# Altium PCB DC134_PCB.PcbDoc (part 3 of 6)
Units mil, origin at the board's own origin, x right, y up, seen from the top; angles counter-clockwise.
Board outline 4000 x 2750 mil, 6 copper layers (L1_Top Layer, L2_GND1, L3_Signal, L4_Plane, L5_GND2, L6_Bottom Layer), stack 60.4 mil thick; 404 components, 244 nets, 1547 pads, 694 vias.
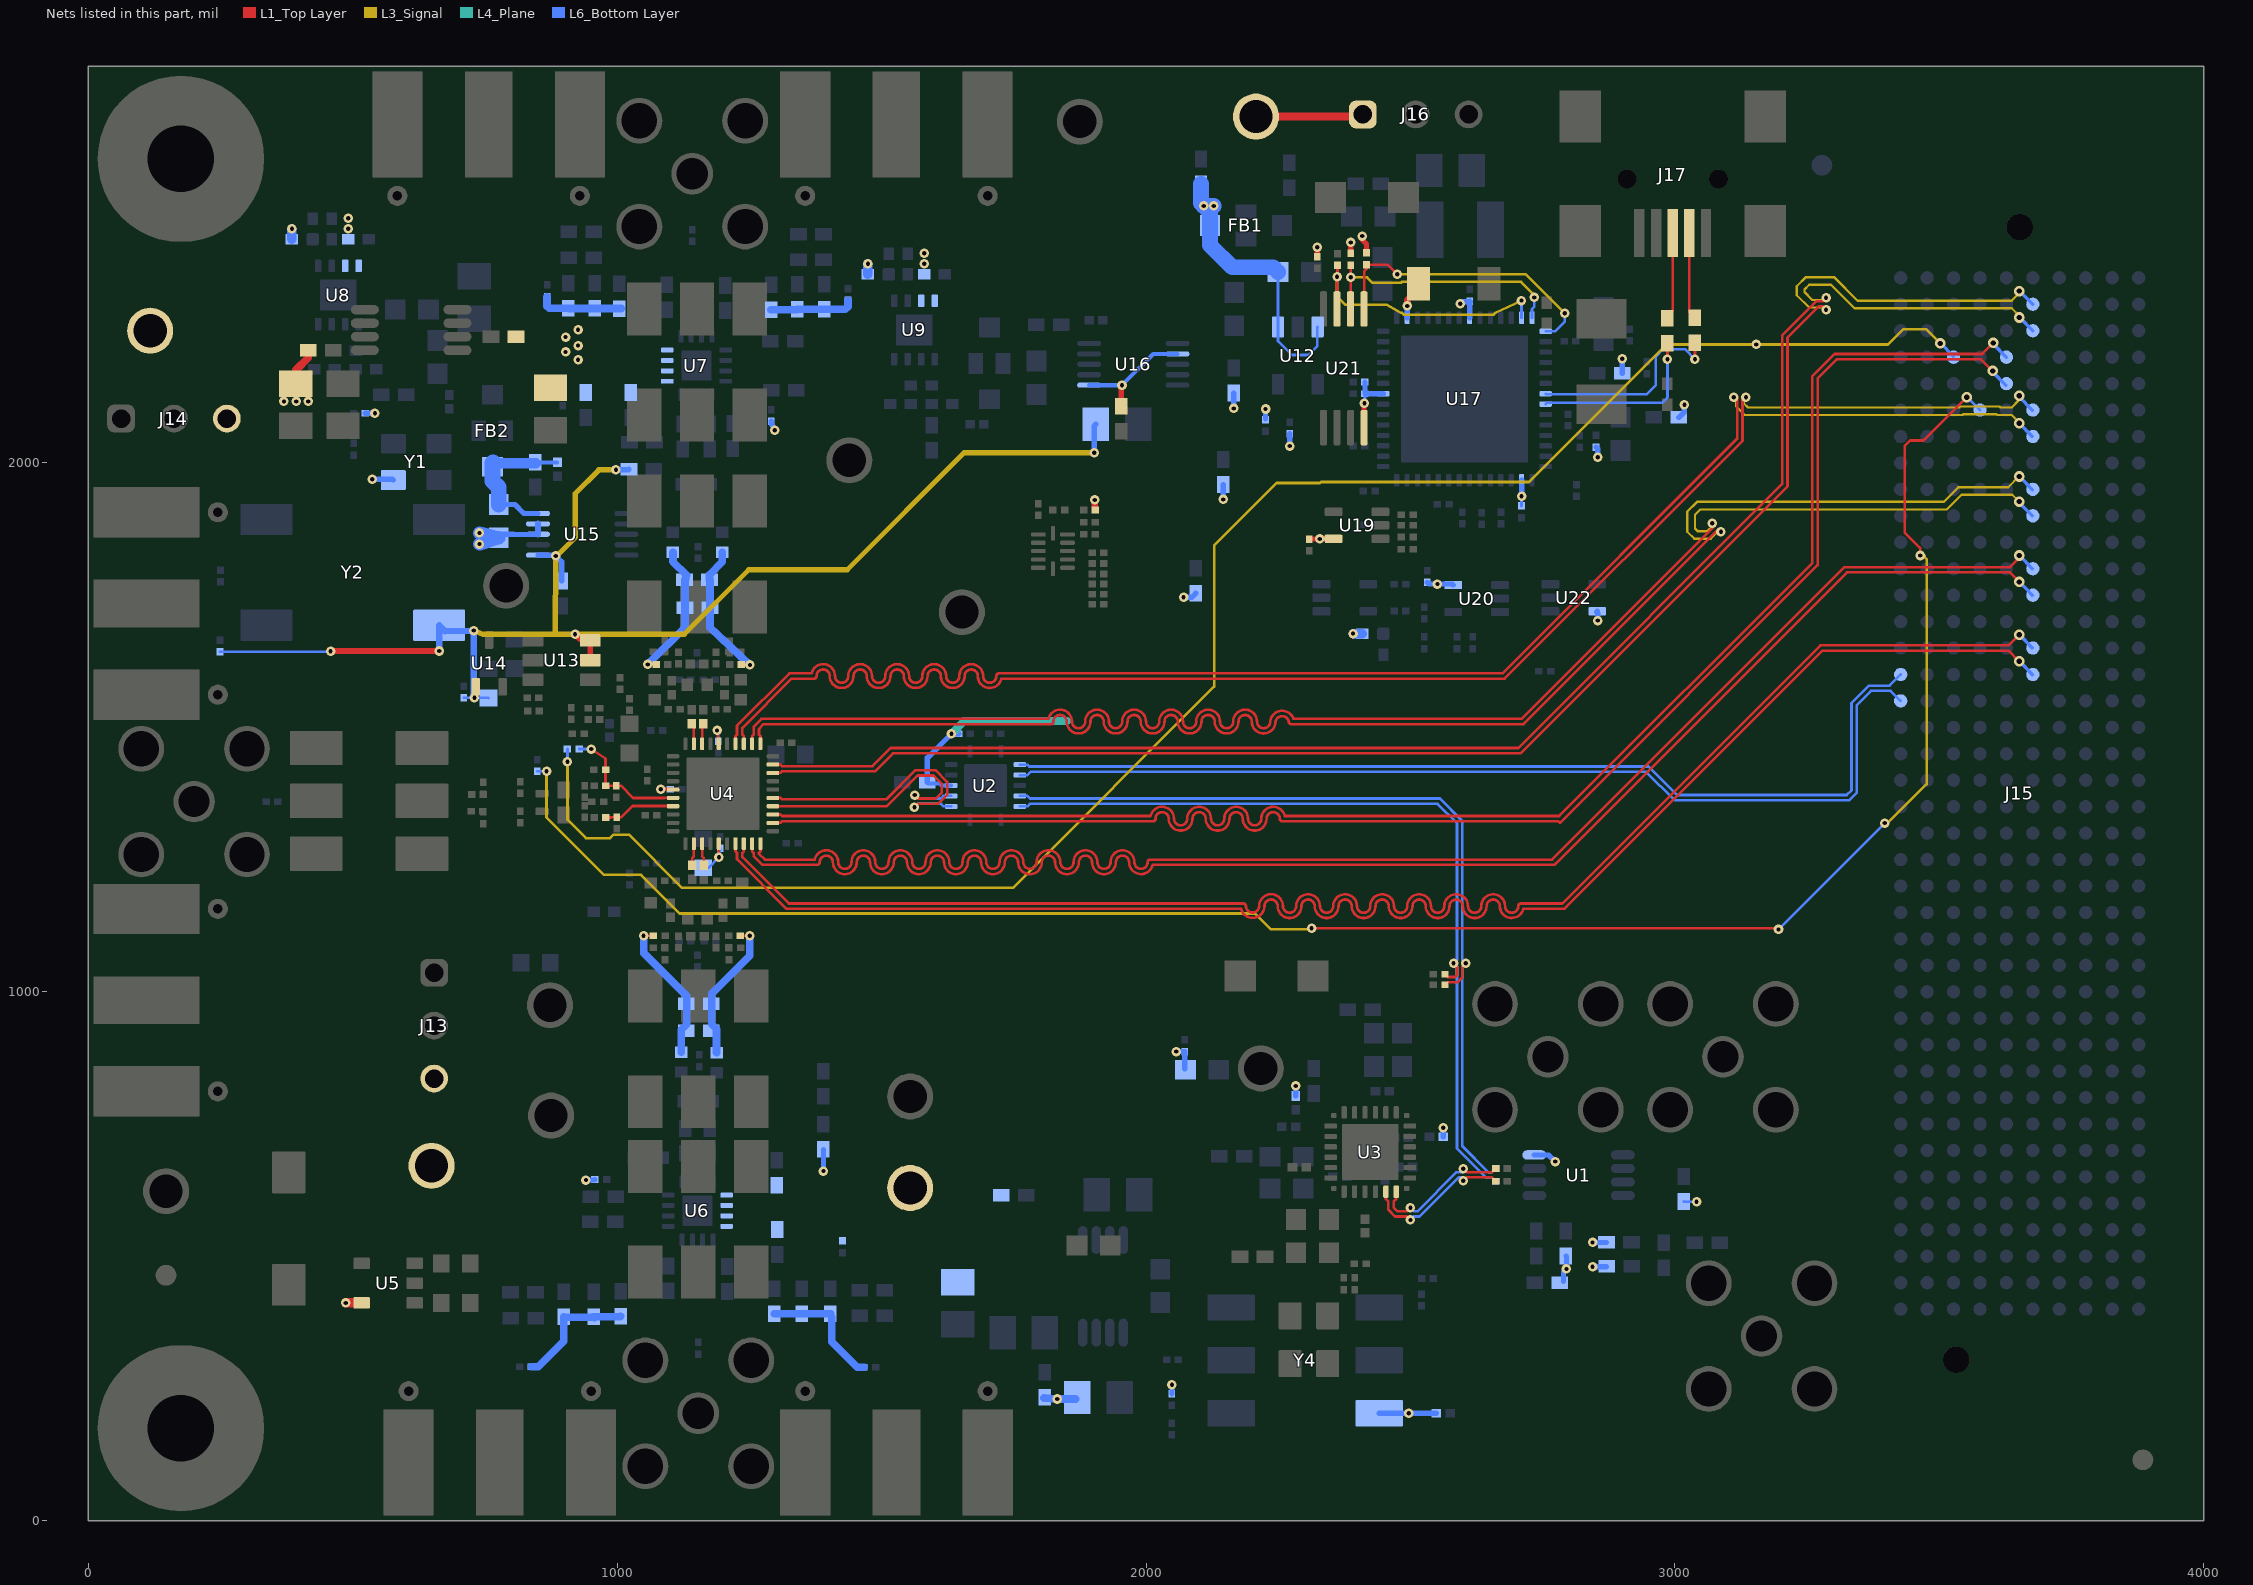
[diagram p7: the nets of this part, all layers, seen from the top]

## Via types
v1: diameter 18, hole 8, L1_Top Layer to L6_Bottom Layer, tented both sides, 448 vias
v2: diameter 20, hole 10, L1_Top Layer to L6_Bottom Layer, tented both sides, 182 vias
v3: diameter 19.68, hole 7.87, L1_Top Layer to L6_Bottom Layer, tented both sides, 42 vias
v4: diameter 19.68, hole 7.87, L1_Top Layer to L6_Bottom Layer, 20 vias
v5: diameter 18, hole 8, L1_Top Layer to L6_Bottom Layer, 2 vias

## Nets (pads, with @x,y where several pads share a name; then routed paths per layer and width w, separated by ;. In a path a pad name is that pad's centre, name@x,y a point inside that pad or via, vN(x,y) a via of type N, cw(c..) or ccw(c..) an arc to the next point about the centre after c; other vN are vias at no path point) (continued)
+3.3V: C18.2 C19.2 C20.2 C22.2 C30.1 C85.1 C86.2 C93.1 C95.1 C97.1 C99.1 C100.1 C102.1 C103.1 C104.1 C105.2 C106.2 C107.2 C120.2 C121.1 C122.1 C123.1 L18.2 L19.1 L20.1 R34.2 R38.2 R42.2 R52.2 R56.2 R57.1 R66.2 R72.2 R85.2 R93.2 R102.2 R108.2 R125.1 R126.1 R152.1 R155.1 R156.2 R157.2 R160.2 R161.2 R162.2 R173.1 U1.8 U2.4 U13.5 U13.6 U14.1 U15.6 U16.2 U16.6 U17.16 U17.36 U17.44 U17.50 U19.5 U20.5 U21.8 U22.5 Y2.4 Y4.6 | length 4585.1
  L1_Top Layer w5: v1@2412.39,2112.39 v1(2413,2113)
  L1_Top Layer w10: v1(920.5,1676) 930.1,1666.4 949.13,1666.4 U13.6@949.13,1664.4 U13.5@949.13,1629 ; C103.1@1954,2108.12 C103.1@1953,2107.12 1953,2145.5 v1(1954.63,2147.13) ; C121.1@2310.39,1856.02 v1@2328,1856.02 ; R162.2@2324,2390.02 v1(2324,2408) ; v1(2328.39,1856.41) U19.5@2354.71,1856.41 U19.5@2356.5,1856.41 ; R161.2@2387,2398.02 v1(2387,2417) ; v1(2409,2429) 2409,2422 2417,2414 R160.2@2417,2397.02 ; U21.8@2412.39,2066.8 v1@2412.39,2112.39
  L1_Top Layer w12: v1(458,1644) 458.39,1644.39 v1(663.39,1644.39) ; R152.1@1903,1910.98 v1(1903,1930) ; v1(2494,2297) 2494,2308 2515.07,2329.07 C104.1@2515.07,2339
  L1_Top Layer w15: C95.1@392.5,2150.01 392.5,2175.73 415.88,2199.11 R126.1@415.88,2213.01
  L3_Signal w10: v1(729,1683) 747,1676 883,1676 ; v1(997.62,1987) 965.38,1987 920.75,1942.38 920.75,1858.96 885.87,1824.08 v1(884,1824.08) 883,1676 ; v1(1902,2019.41) 1656.41,2019.41 1435,1798 1248.74,1798 1126.74,1676 v1(920.5,1676) 883,1676
  L4_Plane w15: v1(1632.19,1488) 1656.19,1512 1851,1512
  L6_Bottom Layer w5: R38.2@249,1642.95 v1@458,1642.95 ; C97.1@709.78,1555.98 v1(730,1555.98) 756.25,1555.98 C99.1@756.78,1555.44 ; v1@882.37,1825.71 v1(884,1824.08) ; v1(2413,2113) 2414.02,2114.02 C107.2@2414.02,2131 ; C106.2@2710,1918.61 2710,1936.71 v1(2710.29,1937) ; C22.2@3017,603.53 v1(3041,603)
  L6_Bottom Layer w8: C18.2@1586.62,1396 1588.62,1394 1610,1394 1613.96,1390.04 U2.4@1631.51,1390.04 ; U16.6@1892.34,2147.13 v1(1954.63,2147.13) 2013.69,2206.18 U16.2@2059.66,2206.18
  L6_Bottom Layer w10: U15.6@850.34,1825.71 v1@882.37,1825.71 ; v1(884,1824.08) 895,1813.08 C102.1@895,1776.62 ; v1(941,644) 956.98,644 R93.2@957.98,645 ; v1(997.62,1987) 1021.28,1987 R102.2@1022.28,1988 ; R108.2@1291.38,2078.98 1291.38,2073.6 1298,2063.35 v1(1298,2062) ; v1(1390,661) R85.2@1390,701.38 ; C18.2@1586.62,1396 1586.62,1442.43 v1(1632.19,1488) R52.2@1645.98,1488 ; v1(1902,2019.41) 1902,2070 C85.1@1905,2073 ; R66.2@2049,240.02 v1(2049,257) ; v1(2057,886.98) C100.1@2073,886.98 R57.1@2073,854.13 ; v1(2071,1746) 2086.62,1746 R156.2@2094,1753.38 ; v1(2146,1931) R157.2@2146,1959.38 ; v1(2166,2103) L18.2@2166,2132.38 ; C123.1@2226,2083.11 v1(2226,2102) ; v1(2272,2032) 2272,2054.89 C86.2@2272.09,2054.98 ; R56.2@2283,802.99 v1(2283,822) ; C120.2@2414.02,2153.12 C107.2@2414.02,2131 2448.32,2131 U17.36@2448.47,2130.84 ; Y4.6@2440.96,203 v1(2497,203) C30.1@2549.01,203 ; U17.44@2493.75,2274.54 2494,2274.79 v1(2494,2297) ; C122.1@2532,1773.98 2534.98,1771 v1(2551,1771) 2579.03,1771 U20.5@2580.82,1769.21 ; R72.2@2561.99,726 v1(2561.99,743.01) ; v1@2596,2305 C105.2@2612,2305 ; U17.50@2611.86,2274.54 2612,2274.68 C105.2@2612,2305 ; v1(2710.29,1937) U17.16@2710.29,1967.46 ; U1.8@2734.34,691.54 2761.44,691.54 v1(2774,678.98) ; C19.2@2789.62,452 2789.62,470.62 v1(2795,476) 2795,499.38 R42.2@2794,500.38 ; v1(2844.38,480.02) C20.2@2870.76,480.02 ; v1(2844.38,526) R34.2@2870.76,526 ; R155.1@2851,2029.98 2854,2026.98 v1(2854,2010.62) ; U22.5@2853.29,1719.41 2852,1718.12 2854,1716.12 v1(2854,1702) ; L20.1@2900.62,2169.5 v1(2900.62,2197) ; L19.1@3007.62,2086 3018,2096.38 v1(3018,2110) ; C105.2@2612,2305 2612.98,2305 C105.2@2612,2305.98 C105.2@2612,2305
  L6_Bottom Layer w12: v1(663.39,1644.39) Y2.4@663.39,1693 674.41,1681.98 v1(729,1683) ; v1(729,1683) 729.05,1556.93 v1(730,1555.98)
  L6_Bottom Layer w15: R125.1@1807.22,231.62 v1(1832,230) C93.1@1867,230
  L6_Bottom Layer w18: v1(2391.66,1677.34) R173.1@2409.29,1677.34
  other v1: 370,2116.22 393,2116.22 415.88,2116.22 2594,2301
+5V: C70.1 C73.2 C77.2 C83.1 FB1.3 R116.2 R118.2 U8.7 U8.8 U9.7 U9.8 U12.1 U12.3 | length 590.4
  L6_Bottom Layer w5: C83.1@2249.5,2361 2249.5,2257.23 U12.1@2249.6,2257.13 2249.6,2230.4 2276,2204 2307,2204 2324,2221 2324,2256.73 U12.3@2324.4,2257.13
  L6_Bottom Layer w18: R116.2@385.11,2422.62 v1(385.11,2442.62) ; R118.2@1474.24,2356.65 v1(1474.24,2376.65)
  L6_Bottom Layer w30: C70.1@2104,2527.38 2104,2491 v1(2109,2486) ; v1(2128,2486) v1(2109,2486) ; C83.1@2249.5,2361 2240.5,2370 2163,2370 2121.09,2411.91 FB1.3@2121.09,2449 2121.09,2473.91 v1(2109,2486)
  other v1: 1580.5,2376.65 1580.5,2396.65 491.37,2442.62 491.37,2462.62
+5V_EXT: J16.1 TP13.1 | length 203.7
  L1_Top Layer w15: TP13.1@2208,2655 2406,2655 J16.1@2410,2659
-0.23V_CHA: C59.1 C60.1 C88.1 R95.2 R123.2 TP10.1 U6.13 U6.14 U6.15 U6.16
-0.23V_CHB: C61.1 C62.1 C90.1 R112.2 R124.2 TP12.1 U7.13 U7.14 U7.15 U7.16
  other v1: 926,2195 902.56,2210 926,2222 902.44,2238 926,2252
AIN_N: R5.2 U4.13 | length 38.8
  L1_Top Layer w5: U4.13@1160.75,1279.54 1160.75,1255.63 1163.85,1252.53 R5.2@1163.85,1242.02
AIN_P: R12.2 U4.12 | length 38.8
  L1_Top Layer w5: R12.2@1141.35,1242.02 1141.9,1252.53 1145,1255.63 U4.12@1145,1279.54
AMP_CHA_IN_N: R13.1 R88.1 R91.2 R92.2 | length 235
  L6_Bottom Layer w14.5: R13.1@838.02,291 850.98,291 899,339.02 R91.2@899,385.38 ; R91.2@901.45,384.38 957.45,384.38 R92.2@957.16,384.02 ; R92.2@955.5,385.38 1005.38,385.38 R88.1@1006.38,386.38
AMP_CHA_IN_P: R2.1 R82.1 R83.1 R86.1 | length 232.8
  L6_Bottom Layer w14.5: R86.1@1297.62,391.24 R83.1@1349.38,391.24 ; R83.1@1349.51,391.38 R82.1@1403.38,391.38 ; R82.1@1405.72,384.38 1405.72,338.02 1453.75,290 R2.1@1466.7,290
AMP_CHA_OUT_N: C52.2 L12.2 R14.1 R87.1 | length 277.1
  L1_Top Layer w5: v1(1050,1106) R14.1@1068.55,1106
  L6_Bottom Layer w14.5: v1(1050,1106) 1050,1073.38 1131.38,992 1131.38,938.38 1120.95,927.95 1120.95,886.26 L12.2@1121.51,885.7
AMP_CHA_OUT_P: C52.1 L11.2 R1.1 R87.2 | length 273.3
  L1_Top Layer w5: R1.1@1232.76,1106 v1(1250.74,1106)
  L6_Bottom Layer w14.5: L11.2@1188.56,884.7 1188,885.26 1188,929 1178.62,938.38 1178.62,996 1250.74,1068.12 v1(1250.74,1106)
AMP_CHB_IN_N: R27.1 R105.1 R109.2 R110.2 | length 160
  L6_Bottom Layer w14.5: R105.1@1291,2289.38 1340,2289.38 R109.2@1341,2290.38 R110.2@1392,2290.38 1431.38,2290.38 1436.5,2295.5 R27.1@1436.5,2307.48
AMP_CHB_IN_P: R16.1 R99.1 R100.1 R103.1 | length 159.2
  L6_Bottom Layer w14.5: R16.1@867.5,2314.48 867.5,2296.5 871.62,2292.38 R99.1@907.7,2292.38 ; R99.1@908.7,2292 R103.1@1008,2292
AMP_CHB_OUT_N: C57.2 L14.2 R28.1 R104.1 | length 256.5
  L6_Bottom Layer w14.5: C57.2@1174.69,1779 1174.69,1788.69 1199.04,1813.04 L14.2@1199.04,1831.3 ; R104.1@1175.69,1727.07 C57.2@1175.69,1779 ; R104.1@1176.69,1727.07 R104.1@1175.62,1726 1175.5,1689 v1(1251,1618)
AMP_CHB_OUT_P: C57.1 L13.2 R15.1 R104.2 | length 251.1
  L6_Bottom Layer w14.5: v1(1058,1619) 1128.38,1689.38 R104.2@1128.38,1726 ; L13.2@1105.47,1831.3 1105.47,1813.53 C57.1@1131.45,1787.55 ; R104.2@1128.45,1727.07 C57.1@1128.45,1779 ; C57.1@1129.45,1779 C57.1@1129.45,1787.55
AVDD: C40.1 C41.1 C42.1 C43.1 J13.3 J14.3 R31.2 R133.1 TP6.1 U4.5 U4.15 U4.36 U5.5 U15.8 U15.9 Y1.4 | length 451.9
  L1_Top Layer w5: v1(1189,1494.09) U4.36@1192.13,1469.49 ; U4.15@1192.24,1280.06 1192.24,1263 1193,1262.24 v1@1193,1255
  L1_Top Layer w7: v1(1082.5,1383) U4.5@1105.63,1382.42
  L1_Top Layer w10: v1(1189,1494.09) v1@1190.32,1492.78
  L1_Top Layer w18: v1(486.8,411.6) U5.5@516.8,411.6
  L6_Bottom Layer w5: C43.1@1163,1234.44 1172.44,1234.44 v1(1192.56,1254.56) C41.1@1195,1270.98 ; C42.1@1191,1474.02 v1@1191,1492.09 ; C41.1@1192.56,1270.54 C41.1@1193,1270.98
  L6_Bottom Layer w7.5: v1(1082.5,1383) C40.1@1099.98,1383
  L6_Bottom Layer w10: R31.2@523.07,2094.07 R31.2@524.07,2094.07 v1(542,2094) ; v1(537,1969) 575.24,1969 Y1.4@576.69,1967.55 ; v1(739.5,1846.58) v1(739.5,1867.58) ; R133.1@776,1858.58 782.5,1865.08 804.1,1865.08 804.42,1864.76 850.02,1864.76 U15.8@850.34,1865.08 ; v1(1189,1494.09) v1@1191,1492.09
  L6_Bottom Layer w12: U15.8@850.34,1865.08 U15.9@850.34,1884.76
  L6_Bottom Layer w25: v1(739.5,1846.58) 745.73,1848.63 R133.1@776,1858.58 744.38,1866.38 v1(739.5,1867.58)
AVDD+: C75.1 C76.1 FB2.3 R133.2 U15.10 | length 285
  L6_Bottom Layer w7: C75.1@845,2001.62 845.63,2000.99 C76.1@887,2000.99
  L6_Bottom Layer w10: R133.2@776,1921.57 806.5,1921.57 823.39,1904.69 U15.10@850.34,1904.45
  L6_Bottom Layer w20: FB2.3@769.09,1999.47 C75.1@846.38,1999.47
  L6_Bottom Layer w30: FB2.3@765,2000.59 764.29,1999.88 764.29,1965.71 776,1954 R133.2@776,1921.57
BIN_N: R26.2 U4.38 | length 38.2
  L1_Top Layer w5: U4.38@1160.75,1474.09 1160.75,1498 1163.85,1501.1 R26.2@1165,1510.98
BIN_P: R19.2 U4.39 | length 38.4
  L1_Top Layer w5: R19.2@1139.98,1510.98 1141.9,1501.1 1145,1498 U4.39@1145,1474.09
CLK_N: C26.2 R54.2 U4.7 | length 136.1
  L1_Top Layer w5: C26.2@978.46,1329.63 988.05,1329.63 988.65,1330.22 R54.2@999,1330.22 1007.8,1330.22 1028.95,1351.38 U4.7@1105.51,1351.38
CLK_P: C21.2 R30.2 R41.2 R46.2 U4.6 | length 246.7
  L1_Top Layer w5: v1(951,1459) 978.02,1441 R30.2@978.02,1420 C21.2@978.02,1390.11 ; C21.2@978.46,1389.67 R46.2@998.44,1389.67 1007.24,1389.67 1030.41,1366.5 1089.33,1366.5 1089.96,1367.13 U4.6@1105.51,1367.13
  L1_Top Layer w12: v1(951,1459) v1@953.87,1459 ; C21.2@978.02,1390.11 C21.2@978.46,1389.67
  L6_Bottom Layer w5: R41.2@928.02,1459 v1(951,1459)
DA0_N: J15.E13 U4.19 | length 3053.9
  L1_Top Layer w5: U4.19@1255.24,1280.06 1255.24,1265.74 1258.11,1262.87 1258.11,1256.86 1274.97,1240 1378,1240 ccw(c1378,1245) 1383,1245 cw(c1395.5,1245) 1408,1245 ccw(c1430.5,1245) 1453,1245 cw(c1465.5,1245) 1478,1245 ccw(c1500.5,1245) 1523,1245 cw(c1535.5,1245) 1548,1245 ccw(c1570.5,1245) 1593,1245 cw(c1605.5,1245) 1618,1245 ccw(c1640.5,1245) 1663,1245 cw(c1675.5,1245) 1688,1245 ccw(c1710.5,1245) 1733,1245 cw(c1745.5,1245) 1758,1245 ccw(c1780.5,1245) 1803,1245 cw(c1815.5,1245) 1828,1245 ccw(c1850.5,1245) 1873,1245 cw(c1885.5,1245) 1898,1245 ccw(c1920.5,1245) 1943,1245 cw(c1955.5,1245) 1968,1245 ccw(c1990.5,1245) 2012.44,1240 2772.14,1240 2775.07,1242.93 3325.14,1793 3634,1793 3651,1776 v2(3651,1775)
  L6_Bottom Layer w6.6: v2@3652,1775 J15.E13@3676,1750.15
DA0_P: J15.E12 U4.20 | length 3041.3
  L1_Top Layer w5: U4.20@1270.98,1280.06 1270.98,1265.74 1268.11,1262.87 1268.11,1261 1279.11,1250 1373.56,1250 cw(c1395.5,1245) 1418,1245 ccw(c1430.5,1245) 1443,1245 cw(c1465.5,1245) 1488,1245 ccw(c1500.5,1245) 1513,1245 cw(c1535.5,1245) 1558,1245 ccw(c1570.5,1245) 1583,1245 cw(c1605.5,1245) 1628,1245 ccw(c1640.5,1245) 1653,1245 cw(c1675.5,1245) 1698,1245 ccw(c1710.5,1245) 1723,1245 cw(c1745.5,1245) 1768,1245 ccw(c1780.5,1245) 1793,1245 cw(c1815.5,1245) 1838,1245 ccw(c1850.5,1245) 1863,1245 cw(c1885.5,1245) 1908,1245 ccw(c1920.5,1245) 1933,1245 cw(c1955.5,1245) 1978,1245 ccw(c1990.5,1245) 2003,1245 cw(c2008,1245) 2008,1250 2768,1250 3321,1803 3634,1803 3651,1820 v2(3651,1825)
  L6_Bottom Layer w6.6: v2@3652,1825 J15.E12@3676,1800.15
DA1_N: J15.E16 U4.17 | length 3034.6
  L1_Top Layer w5: U4.17@1223.74,1280.06 1223.74,1265.74 1226.61,1262.87 1226.61,1250.86 1320.47,1157 2179.64,1157 ccw(c2201.5,1162.32) 2224,1161.91 ; 2224,1162 cw(c2236.5,1162) 2249,1162 ccw(c2271.5,1162) 2294,1162 cw(c2306.5,1162) 2319,1162 ccw(c2341.5,1162) 2364,1162 cw(c2376.5,1162) 2389,1162 ccw(c2411.5,1162) 2434,1162 cw(c2446.5,1162) 2459,1162 ccw(c2481.5,1162) 2504,1162 cw(c2516.5,1162) 2529,1162 ccw(c2551.5,1162) 2574,1162 cw(c2586.5,1162) 2599,1162 ccw(c2621.5,1162) 2644,1162 cw(c2656.5,1162) 2669,1162 ccw(c2691.5,1162) 2713.44,1157 2791.49,1157 2794.42,1159.93 3279.49,1645 3631,1645 3651,1625 v2(3651,1624.78)
  L6_Bottom Layer w6.6: v2@3652,1624.78 J15.E16@3676,1599.92
DA1_P: J15.E15 U4.18 | length 3021.3
  L1_Top Layer w5: U4.18@1239.49,1280.06 1239.49,1265.74 1236.61,1262.87 1236.61,1255 1324.61,1167 2184,1167 cw(c2184,1162) 2189,1162.09 ; 2189,1162 ccw(c2184,1162) 2189,1162.09 ; 2214,1162 cw(c2236.5,1162) 2214,1162.05 ; v2(3651,1675) 3631,1655 3275.35,1655 2787.35,1167 2709,1167 ccw(c2709,1162) 2704,1162 cw(c2691.5,1162) 2679,1162 ccw(c2656.5,1162) 2634,1162 cw(c2621.5,1162) 2609,1162 ccw(c2586.5,1162) 2564,1162 cw(c2551.5,1162) 2539,1162 ccw(c2516.5,1162) 2494,1162 cw(c2481.5,1162) 2469,1162 ccw(c2446.5,1162) 2424,1162 cw(c2411.5,1162) 2399,1162 ccw(c2376.5,1162) 2354,1162 cw(c2341.5,1162) 2329,1162 ccw(c2306.5,1162) 2284,1162 cw(c2271.5,1162) 2259,1162 ccw(c2236.5,1162) 2214,1162.05 ; 2189,1162.09 ccw(c2201.5,1162.32) 2214,1162.05
  L6_Bottom Layer w6.6: v2@3652,1675 J15.E15@3676,1650.15
DB0_N: J15.E10 U4.32 | length 3005.6
  L1_Top Layer w5: U4.32@1255.24,1469.03 1255.24,1483.34 1258.11,1486.22 1258.11,1501.14 1272.97,1516 1815.56,1516 cw(c1837.5,1511) 1860,1511 ccw(c1872.5,1511) 1885,1511 cw(c1907.5,1511) 1930,1511 ccw(c1942.5,1511) 1955,1511 cw(c1977.5,1511) 2000,1511 ccw(c2012.5,1511) 2025,1511 cw(c2047.5,1511) 2070,1511 ccw(c2082.5,1511) 2095,1511 cw(c2117.5,1511) 2140,1511 ccw(c2152.5,1511) 2165,1511 cw(c2187.5,1511) 2210,1511 ccw(c2222.5,1511) 2235,1511 ; 2235.04,1511.65 cw(c2257.5,1508.72) 2278.95,1516 2710,1516 3074,1880 3074,1883 v1(3070.9,1886.1)
  L3_Signal w4.4: v1(3070.9,1886.1) 3070.9,1880.02 3061.94,1871.06 3042.94,1871.06 3038,1876 3038,1902 3048,1912 3514.29,1912 3542.1,1939.82 3638,1939.82 v2(3651,1927)
  L6_Bottom Layer w6.6: v2@3651,1925 J15.E10@3676,1900
DB0_P: J15.E9 U4.31 | length 3062.8
  L1_Top Layer w5: U4.31@1270.98,1469.03 1270.98,1483.34 1268.11,1486.22 1268.11,1497 1277.11,1506 1820,1506 ccw(c1820,1511) 1825,1511 cw(c1837.5,1511) 1850,1511 ccw(c1872.5,1511) 1895,1511 cw(c1907.5,1511) 1920,1511 ccw(c1942.5,1511) 1965,1511 cw(c1977.5,1511) 1990,1511 ccw(c2012.5,1511) 2035,1511 cw(c2047.5,1511) 2060,1511 ccw(c2082.5,1511) 2105,1511 cw(c2117.5,1511) 2130,1511 ccw(c2152.5,1511) 2175,1511 cw(c2187.5,1511) 2200,1511 ccw(c2222.5,1511) 2245,1510.63 cw(c2257.5,1508.72) 2270.04,1510.38 ccw(c2275,1511) 2275,1506 2714.14,1506 3081.07,1872.93 3084.07,1872.93 v1(3087.17,1869.83)
  L3_Signal w4.4: v1(3087.17,1869.83) 3081.09,1869.83 3067.91,1856.66 3036.98,1856.66 3023.6,1870.04 3023.6,1907.96 3042.04,1926.4 3508.32,1926.4 3536.14,1954.22 3630.25,1954.22 3650.45,1974.42 v2(3651,1974.42)
  L6_Bottom Layer w6.6: v2@3652,1974.42 J15.E9@3676,1949.57
DB1_N: J15.E7 U4.34 | length 3038.3
  L1_Top Layer w5: U4.34@1223.74,1469.03 1223.74,1483.34 1226.61,1486.22 1226.61,1503.14 1325.47,1602 1367.56,1602 cw(c1389.5,1597) 1412,1597 ccw(c1424.5,1597) 1437,1597 cw(c1459.5,1597) 1482,1597 ccw(c1494.5,1597) 1507,1597 cw(c1529.5,1597) 1552,1597 ccw(c1564.5,1597) 1577,1597 cw(c1599.5,1597) 1622,1597 ccw(c1634.5,1597) 1647,1597 cw(c1669.5,1597) 1692,1597 ccw(c1704.5,1597) 1717,1597 cw(c1722,1597) 1722,1602 2674,1602 3118,2046 3118,2122 3115.66,2124.34 v1(3111.5,2124.34)
  L3_Signal w4.4: v1(3111.5,2124.34) 3115.8,2120.04 3115.8,2107.04 3132.24,2090.6 3544.02,2090.6 3545.62,2092.2 3608.12,2092.2 3609.72,2090.6 3637,2090.6 3651,2076.6 v2(3651,2075)
  L6_Bottom Layer w6.6: v2(3651,2075) J15.E7@3676,2050
DB1_P: J15.E6 U4.33 | length 3020.9
  L1_Top Layer w5: U4.33@1239.49,1469.03 1239.49,1483.34 1236.61,1486.22 1236.61,1499 1329.61,1592 1372,1592 ccw(c1372,1597) 1377,1597 cw(c1389.5,1597) 1402,1597 ccw(c1424.5,1597) 1447,1597 cw(c1459.5,1597) 1472,1597 ccw(c1494.5,1597) 1517,1597 cw(c1529.5,1597) 1542,1597 ccw(c1564.5,1597) 1587,1597 cw(c1599.5,1597) 1612,1597 ccw(c1634.5,1597) 1657,1597 cw(c1669.5,1597) 1682,1597 ccw(c1704.5,1597) 1726.44,1592 2678.14,1592 3128,2041.86 3128,2122 3130.34,2124.34 v1(3134.5,2124.34)
  L3_Signal w4.4: v1(3134.5,2124.34) 3130.2,2120.04 3130.2,2113 3138.2,2105 3538.05,2105 3539.65,2106.6 3614.09,2106.6 3615.69,2105 3637,2105 3651,2119 v2(3651,2127)
  L6_Bottom Layer w6.6: v2@3651,2125 J15.E6@3676,2100
DCLK_N: J15.F5 U4.22 | length 3063.9
  L1_Top Layer w5: U4.22@1294.49,1319.2 U4.22@1294.49,1319.88 ; U4.22@1294.61,1319.43 1308.92,1319.43 1311.79,1322.3 1659.91,1322.3 1660.11,1322.5 1673.78,1322.5 1673.98,1322.3 2013,1322.3 ccw(c2013,1327.3) 2018,1327.3 cw(c2030.5,1327.3) 2043,1327.3 ccw(c2065.5,1327.3) 2088,1327.3 cw(c2100.5,1327.3) 2113,1327.3 ccw(c2135.5,1327.3) 2158,1327.3 cw(c2170.5,1327.3) 2183,1327.3 ccw(c2205.5,1327.3) 2228,1327.3 cw(c2240.5,1327.3) 2253,1327.3 ccw(c2258,1327.3) 2258,1322.3 2779.69,1322.3 2782.57,1319.43 3270,1806.86 3270,2160 3306,2196 3579,2196 v2(3601,2174)
  L6_Bottom Layer w6.6: v2@3601,2172 J15.F5@3626,2147
DCLK_P: J15.F4 U4.23 | length 3058.2
  L1_Top Layer w5: U4.23@1294.61,1335.17 1308.92,1335.17 1311.79,1332.3 1655.77,1332.3 1655.97,1332.5 1677.92,1332.5 1678.12,1332.3 2008.56,1332.3 cw(c2030.5,1327.3) 2053,1327.3 ccw(c2065.5,1327.3) 2078,1327.3 cw(c2100.5,1327.3) 2123,1327.3 ccw(c2135.5,1327.3) 2148,1327.3 cw(c2170.5,1327.3) 2193,1327.3 ccw(c2205.5,1327.3) 2218,1327.3 cw(c2240.5,1327.3) 2262.44,1332.3 2781.3,1332.3 3260,1811 3260,2164.14 3301.86,2206 3581,2206 v2(3602,2227)
  L6_Bottom Layer w6.6: v2@3602,2225 J15.F4@3627,2200
DCLKIN_CDC_N: R32.2 U3.6 | length 274.7
  L1_Top Layer w5: U3.6@2473.21,622.2 2473.21,607.89 2468.37,603.04 2468.37,592 2475.37,585 2493.5,585 v1(2500,591.5) ; v1(2600,665.5) 2606.5,659 2653.98,659 R32.2@2660.98,666
  L6_Bottom Layer w5: v1(2500,591.5) 2506.5,585 2513,585 2587,659 2598,659 2600,661 v1(2600,665.5)
DCLKIN_CDC_P: R40.2 U3.5 | length 291.2
  L1_Top Layer w5: U3.5@2453.53,622.2 2453.53,607.89 2458.37,603.04 2458.37,587.86 2471.23,575 2493.5,575 v1(2500,568.5) ; v1(2600,642.5) 2606.5,649 2653.98,649 R40.2@2660.98,642
  L6_Bottom Layer w5: v1(2500,568.5) 2506.5,575 2517.14,575 2591.14,649 2598,649 2600,647 v1(2600,642.5)
DCLKIN_FPGA_N: J15.K16 U2.9 | length 1880.5
  L6_Bottom Layer w5: U2.9@1761.44,1429.41 1775.75,1429.41 1779.16,1426 2950,1426 3003.99,1372.01 3325.01,1372.01 3334,1381 3334,1546.14 3363.93,1576.07 3366.86,1579 3406,1579 J15.K16@3427,1600
DCLKIN_FPGA_P: J15.K17 U2.10 | length 1881
  L6_Bottom Layer w5: U2.10@1761.44,1409.73 1775.75,1409.73 1782.02,1416 2945.86,1416 2999.84,1362.01 ; 2999.93,1361.93 2999.84,1362.01 ; J15.K17@3427,1550 3408,1569 3371,1569 3344,1542 3344,1376.86 3329.16,1362.01 2999.84,1362.01
DCLKIN_N: U2.3 U4.24 | length 498.5
  L1_Top Layer w5: U4.24@1294.61,1350.92 1509.92,1350.92 1568,1409 1598,1409 1614,1393 1614,1376.51 1603,1365.51 1569.25,1365.51 v1(1562.75,1372.01)
  L6_Bottom Layer w5: v1(1562.75,1372.01) 1569.25,1365.51 1612.36,1365.51 1617.2,1370.36 U2.3@1631.51,1370.36
DCLKIN_P: U2.2 U4.25 | length 532.9
  L1_Top Layer w5: U4.25@1294.61,1366.67 1308.92,1366.67 1311.52,1364.07 1508.93,1364.07 1563.86,1419 1602.14,1419 1624,1397.14 1624,1372.37 1607.14,1355.51 1568.5,1355.51 v1(1562,1349.01)
  L6_Bottom Layer w5: v1(1562,1349.01) 1568.5,1355.51 1612.36,1355.51 1617.2,1350.67 U2.2@1631.51,1350.67
DCLKIN_SMA_N: R35.2 R64.2 U2.12 | length 1630.9
  L1_Top Layer w5: R64.2@2565.38,1013.02 2570.35,1018 2589.14,1018 2598,1026.86 2598,1047.5 v1(2604.5,1054)
  L6_Bottom Layer w5: U2.12@1761.44,1370.36 1775.75,1370.36 1780.59,1365.51 2555.49,1365.51 2598,1323 2598,1060.5 v1(2604.5,1054) 2598,1047.5 2598,708 2647,659 2653.98,659 R35.2@2660.98,666
DCLKIN_SMA_P: R36.2 R61.2 U2.13 | length 1614.4
  L1_Top Layer w5: R61.2@2565.38,1033.02 2570.4,1028 2585,1028 2588,1031 2588,1047.5 v1(2581.5,1054)
  L6_Bottom Layer w5: U2.13@1761.44,1350.67 1775.75,1350.67 1780.59,1355.51 2551.34,1355.51 2588,1318.86 2588,1060.5 v1(2581.5,1054) 2588,1047.5 2588,703.86 2642.86,649 2653.98,649 R36.2@2660.98,642
DM-CON: J17.2 R147.1 | length 143.5
  L1_Top Layer w5: J17.2@3027.5,2416.64 3027.5,2285.13 R147.1@3036,2276.62
DM-FTDI: R147.2 U17.7 | length 388.9
  L1_Top Layer w5: v1(3038,2196) R147.2@3038,2227.38
  L6_Bottom Layer w5: U17.7@2755.56,2130.84 2756.4,2130 2947,2130 2964,2147 2964,2201 2978,2215 3019,2215 v1(3038,2196)
DP-CON: J17.3 R150.1 | length 146
  L1_Top Layer w5: R150.1@2984,2275.62 2996,2287.62 J17.3@2996,2416.64
DP-FTDI: R150.2 U17.8 | length 338.3
  L1_Top Layer w5: v1(2986,2196) R150.2@2986,2226.38
  L6_Bottom Layer w5: U17.8@2755.56,2111.16 2758.08,2113.68 2976,2113.68 2986,2123.68 v1(2986,2196)
EECLK: R161.1 U17.56 U21.2 | length 490.3
  L1_Top Layer w5: U21.2@2386.8,2291.2 2387,2291.41 v1(2387,2351) R161.1@2387,2374
  L3_Signal w5: v1(2387,2351) 2418,2351 2428.5,2340.5 2481.83,2340.5 2483.83,2342.5 2709.5,2342.5 2734,2318 v1(2734,2313)
  L6_Bottom Layer w5: U17.56@2729.97,2274.54 2729.97,2291 2734,2295.03 v1(2734,2313)
EECS: R160.1 U17.1 U21.1 | length 558.5
  L1_Top Layer w5: U21.1@2412.39,2291.2 2412.39,2362 2417,2366.61 R160.1@2417,2374.98 2457.02,2374.98 v1(2475,2357)
  L3_Signal w5: v1(2475,2357) 2718,2357 v1(2792,2283)
  L6_Bottom Layer w5: U17.1@2755.56,2248.95 2773.62,2248.95 2792,2267.33 v1(2792,2283)
EEDATA: R164.2 U17.55 U21.3 | length 520.3
  L1_Top Layer w5: U21.3@2361.2,2291.2 v1(2361.2,2352.2) 2362,2353 R164.2@2362,2373.98
  L3_Signal w5: v1(2361.2,2352.2) 2361.2,2314.8 2377,2299 2455,2299 2481.83,2284 2483.67,2284 2487.17,2280.5 2657.33,2280.5 2660.83,2284 v1(2710,2307)
  L6_Bottom Layer w5: v1(2710,2307) 2710,2274.83 U17.55@2710.29,2274.54
FCLK_N: J15.E3 U4.29 | length 3051
  L1_Top Layer w5: U4.29@1294.61,1429.66 1308.92,1429.66 1311.79,1426.79 1483,1426.79 1517.21,1461 2704,1461 3203,1960 3203,2241.14 3267.86,2306 3279.5,2306 v1(3286,2312.5)
  L3_Signal w4.4: v1(3286,2312.5) 3281.7,2308.2 3260,2308.2 3245,2323.2 3245,2328 3254,2337 3295,2337 3339.6,2292.4 3416.09,2292.4 3416.29,2292.6 3637,2292.6 3651,2278.6 v2(3651,2275)
  L6_Bottom Layer w6.6: v2@3652,2275 J15.E3@3677,2250
FCLK_P: J15.E2 U4.28 | length 3099.1
  L1_Top Layer w5: U4.28@1294.61,1413.91 1308.92,1413.91 1311.79,1416.79 1487.14,1416.79 1521.35,1451 2708.14,1451 3213,1955.86 3213,2237 3272,2296 3279.5,2296 v1(3286,2289.5)
  L3_Signal w4.4: v1(3286,2289.5) 3281.7,2293.8 3254.04,2293.8 3230.6,2317.24 3230.6,2333.96 3248.04,2351.4 3300.96,2351.4 3345.56,2306.8 3410.12,2306.8 3410.32,2307 3637,2307 3651,2321 v2(3651,2325)
  L6_Bottom Layer w6.6: v2@3652,2325 J15.E2@3677,2300
FPGA_CLK: J15.H4 R41.1 | length 3429.5
  L3_Signal w5: v1(906,1435) 906,1325.5 941,1290.5 986.83,1290.5 993.33,1297 1022,1297 1122,1197 1749,1197 2129,1577 2129,1844 2247,1962 2329,1962 2331,1964 2724,1964 2984,2224 v1(3154,2224) 3403,2224 3432,2253 3475,2253 v2(3502,2226)
  L6_Bottom Layer w5: v1(906,1435) R41.1@905.98,1459 ; v1@3151.83,2224 v1(3154,2224)
  L6_Bottom Layer w6.6: v2@3503,2226 J15.H4@3526.75,2201.41
FPGA_REFCLK: J15.G6 R29.2 | length 3769.2
  L1_Top Layer w5: v1(2313,1120) 3194,1120 v1(3196,1118) ; v1(3464,1825) 3464,1839.25 3434.5,1868.75 3434.5,2032.25 3444.75,2042.5 3470.16,2042.5 v2(3552,2124.34)
  L3_Signal w5: v1(866.53,1416.98) 866.53,1329.85 975.38,1221 1045,1221 1118,1148 2206,1148 2236,1118 2311,1118 v1(2313,1120) ; v1(3397,1319) 3402,1319 3476,1393 3476,1818 3472.08,1821.92 3472.08,1825 v1(3464,1825)
  L6_Bottom Layer w5: R29.2@849.15,1416.98 v1(866.53,1416.98) ; v1(3196,1118) v1(3397,1319) ; v2(3552,2124.34) 3552.66,2124.34 J15.G6@3577,2100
